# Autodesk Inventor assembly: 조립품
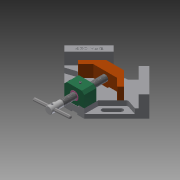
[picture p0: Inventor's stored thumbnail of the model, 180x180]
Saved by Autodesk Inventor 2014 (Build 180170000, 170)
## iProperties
Created: 2019-04
Part Number: 조립품
Document SubType Name: Assembly
Designer: kh
Author: kh
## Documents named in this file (11)
- C:\Users\kh\Desktop\490407V1024\조립품.iam
- C:\Users\kh\Desktop\490407V1024\본체.ipt
- C:\Users\kh\Desktop\490407V1024\리드스크류.ipt
- C:\Users\kh\Desktop\490407V1024\멈춤나사 M4x5.ipt
- C:\Users\kh\Desktop\490407V1024\멈춤나사 M4x10.ipt
- C:\Users\kh\Desktop\490407V1024\볼트 M4x16.ipt
- C:\Users\kh\Desktop\490407V1024\부시.ipt
- C:\Users\kh\Desktop\490407V1024\서포트.ipt
- C:\Users\kh\Desktop\490407V1024\조.ipt
- C:\Users\kh\Desktop\490407V1024\평행 핀 2.5x24.ipt
- C:\Users\kh\Desktop\490407V1024\핸들.ipt
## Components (1 placed, 1 different names)
1. 핸들:1 — Mate:4, Mate:5, Mate:6
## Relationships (3: Mate 3)
- Mate:4: 핸들:1
- Mate:5: 핸들:1
- Mate:6: 핸들:1
